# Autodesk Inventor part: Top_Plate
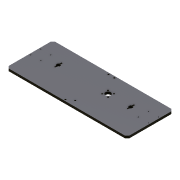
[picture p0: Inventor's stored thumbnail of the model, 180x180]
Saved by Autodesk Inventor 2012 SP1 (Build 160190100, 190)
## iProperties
Created: 2005-12
Part Number: Top_Plate
Document SubType Name: Modeling
Designer: t_munrn
Density: 1 g/cm^3
Material: Default
Author: t_munrn
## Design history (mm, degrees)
sketch "Sketch1"
  geometry: L1 (-325, 125)-(325, 125); L2 (325, 125)-(325, -125); L3 (325, -125)-(-325, -125); L4 (-325, -125)-(-325, 125); L5 (-325, -125)-(325, 125); L6 (263.088, 51.787)-(317.063, 51.787); L7 (317.063, 51.787)-(317.063, -2.188); L8 (317.063, -2.188)-(263.088, -2.188); L9 (263.088, -2.188)-(263.088, 51.787); 6 further points
  constraints: 18 end point, 5 coincident, 4 parallel, 3 perpendicular, 2 horizontal, 1 midpoint
  dimensions: "d0" = 250 distance of L3.end L1.start; "d1" = 650 distance of L1.start L1.end; "d2" = 2.188 distance from line of L8 point (0, 0); "d3" = 53.975 distance of L6.end L7.end; "d4" = 263.088 distance from line of point (0, 0) L9
extrude "Extrusion1" new body sketch "Sketch1" distance "d5" = 12.7; taper "d6" = 0 deg
hole "Hole1" sketch "Sketch1" diameter "d7" = 4.917; stored, may be unused: countersink angle "d11" = 90 deg, drill point angle "d13" = 118 deg; dims "d8" = 6, "d9" = 4, "d10" = 2, "d12" = 8
sketch "Sketch2"
  geometry: L1 (-325, 125)-(325, 125) reference; L2 (325, -125)-(-325, -125) reference; L3 (0, 125)-(0, -125); L4 (-15.875, 115.475)-(15.875, 115.475); L5 (-15.4, -117)-(15.4, -95); 7 further points
  constraints: 6 end point, 4 coincident, 4 midpoint, 2 point on line, 1 perpendicular
  dimensions: "d14" = 9.525 distance between parallel lines of L1 L4; "d15" = 31.75 distance of L4.start L4.end; "d16" = 30.8 horizontal distance of L5.start L5.end; "d17" = 8 distance from line of L2 point (-15.4, -117); "d18" = 22 vertical distance of L5.start L5.end
hole "Hole2" sketch "Sketch2" at (-15.4, -117), (15.4, -95), (15.875, 115.475), (-15.875, 115.475) diameter "d19" = 4.2; stored, may be unused: countersink angle "d23" = 90 deg, drill point angle "d25" = 118 deg; dims "d20" = 6, "d21" = 8, "d22" = 4.5, "d24" = 8
sketch "Sketch3"
  geometry: L1 (56.9, 40.675)-(88.65, 40.675); L2 (88.65, 40.675)-(88.65, 8.925); L3 (88.65, 8.925)-(56.9, 8.925); L4 (56.9, 8.925)-(56.9, 40.675); L5 (56.9, 8.925)-(88.65, 40.675); C1 r 14.287 at (72.775, 24.8); 3 further points
  constraints: 10 end point, 4 coincident, 2 parallel, 2 perpendicular, 1 centre point, 1 horizontal, 1 midpoint
  dimensions: "d26" = 31.75 distance of L1.start L1.end; "d27" = 56.9 distance from line of point (0, 0) L4; "d28" = 8.925 distance from line of L3 point (0, 0); "d36" = 28.575 diameter of C1
hole "Hole3" sketch "Sketch3" diameter "d29" = 4.2; stored, may be unused: countersink angle "d33" = 90 deg, drill point angle "d35" = 118 deg; dims "d30" = 6, "d31" = 8, "d32" = 4.5, "d34" = 8
extrude "Extrusion2" cut sketch "Sketch3" stored distance "d37" = 10; taper "d38" = 0 deg
sketch "Sketch4"
  geometry: L1 (191.45, 41.3)-(198.55, 41.3); L2 (198.55, 41.3)-(198.55, 8.3); L3 (198.55, 8.3)-(191.45, 8.3); L4 (191.45, 8.3)-(191.45, 41.3); C1 r 14.287 at (72.775, 24.8) reference; C2 r 9.525 at (195, 24.8); A1 r 3.55 centre (195, 41.3) between (198.55, 41.3) and (191.45, 41.3); A2 r 3.55 centre (195, 8.3) between (191.45, 8.3) and (198.55, 8.3); 3 further points
  constraints: 8 end point, 4 point on circle, 4 tangent, 3 centre point, 2 horizontal alignment, 2 midpoint, 2 parallel, 1 horizontal, 1 perpendicular, 1 vertical alignment
  dimensions: "d39" = 19.05 diameter of C2; "d40" = 195 horizontal distance of C2.centre point (0, 0); "d41" = 33 distance of L3.end L1.start; "d43" = 7.1 distance between parallel lines of L4 L2
extrude "Extrusion3" cut sketch "Sketch4" stored distance "d44" = 10; taper "d45" = 0 deg
extrude "Extrusion4" cut sketch "Sketch4" distance "d46" = 4; taper "d47" = 0 deg
sketch "Sketch5"
  geometry: L1 (0, -12.7)-(650, -12.7) reference; L2 (650, 0)-(650, -12.7) reference; L3 (650, -6.35)-(590, -6.35); 1 further point
  constraints: 2 end point, 1 coincident, 1 midpoint, 1 parallel
  dimensions: "d48" = 60 distance of L3.start L3.end
hole "Hole4" sketch "Sketch5" at (590, -6.35) diameter "d49" = 4.959; stored, may be unused: countersink angle "d53" = 90 deg, drill point angle "d55" = 118 deg; dims "d50" = 8, "d51" = 8, "d52" = 4.5, "d54" = 12
workplane "Work Plane2"
mirror "Mirror1"
chamfer "Chamfer1" distance "d56" = 12; stored, may be unused: second distance "d57" = 2, angle "d58" = 45 deg
workplane "Work Plane1"
body "Solid1"
workplane "Work Plane3"
